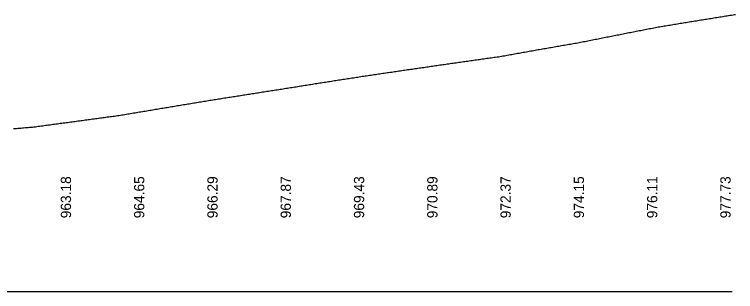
# Model space of a CAD drawing. Extents: x 1619269 to 1623088, y 1189107 to 1192385.
# Drawn here: x 1622586.5 to 1623078.6, y 1190356.6 to 1190545.7 of the extents above; entities that cross this region are included whole.
import ezdxf

# ---------------------------------------------------------------- set-up
doc = ezdxf.new("R2010")
doc.units = 0
for name, color, linetype in [('RD_DDB_Profile_EX', 7, 'Continuous'), ('RD_DDB_StripGrade', 7, 'Continuous'), ('RD_GPK_Profile_Cell', 7, 'Continuous')]:
    doc.layers.add(name, color=color, linetype=linetype)

msp = doc.modelspace()

# ---------------------------------------------------------------- linework, layer by layer
at = {"layer": 'RD_DDB_Profile_EX'}
for points in [[(1623024.84, 1190536.95), (1623025.84, 1190537.13), (1623026.84, 1190537.29), (1623027.84, 1190537.46), (1623028.84, 1190537.62), (1623029.84, 1190537.79), (1623030.84, 1190537.95), (1623031.84, 1190538.12), (1623032.84, 1190538.28), (1623033.84, 1190538.45), (1623034.84, 1190538.61), (1623035.84, 1190538.78), (1623036.84, 1190538.94), (1623037.84, 1190539.1), (1623038.84, 1190539.27), (1623039.84, 1190539.43), (1623040.84, 1190539.59), (1623041.84, 1190539.76), (1623042.84, 1190539.92), (1623043.84, 1190540.08), (1623044.84, 1190540.25), (1623045.84, 1190540.41), (1623046.84, 1190540.57), (1623047.84, 1190540.73), (1623048.84, 1190540.9), (1623049.84, 1190541.06), (1623050.84, 1190541.22), (1623051.84, 1190541.38), (1623052.84, 1190541.54), (1623053.84, 1190541.71), (1623054.84, 1190541.87), (1623055.84, 1190542.03), (1623056.84, 1190542.19), (1623057.84, 1190542.35), (1623058.84, 1190542.51), (1623059.84, 1190542.67), (1623060.84, 1190542.83), (1623061.84, 1190543), (1623062.84, 1190543.16), (1623063.84, 1190543.32), (1623064.84, 1190543.48), (1623065.84, 1190543.64), (1623066.84, 1190543.8), (1623067.84, 1190543.96), (1623068.84, 1190544.12), (1623069.84, 1190544.28), (1623070.84, 1190544.44), (1623071.84, 1190544.6), (1623072.84, 1190544.75), (1623073.84, 1190544.91), (1623074.84, 1190545.07), (1623075.84, 1190545.23), (1623076.84, 1190545.39), (1623077.84, 1190545.55), (1623078.57, 1190545.66)], [(1622924.84, 1190518.24), (1622925.84, 1190518.42), (1622926.84, 1190518.6), (1622927.84, 1190518.78), (1622928.84, 1190518.96), (1622929.84, 1190519.14), (1622930.84, 1190519.32), (1622931.84, 1190519.5), (1622932.84, 1190519.67), (1622933.84, 1190519.85), (1622934.84, 1190520.03), (1622935.84, 1190520.21), (1622936.84, 1190520.39), (1622937.84, 1190520.56), (1622938.84, 1190520.74), (1622939.84, 1190520.92), (1622940.84, 1190521.1), (1622941.84, 1190521.27), (1622942.84, 1190521.45), (1622943.84, 1190521.63), (1622944.84, 1190521.8), (1622945.84, 1190521.98), (1622946.84, 1190522.16), (1622947.84, 1190522.33), (1622948.84, 1190522.51), (1622949.84, 1190522.68), (1622950.84, 1190522.86), (1622951.84, 1190523.04), (1622952.84, 1190523.21), (1622953.84, 1190523.39), (1622954.84, 1190523.56), (1622955.84, 1190523.74), (1622956.84, 1190523.91), (1622957.84, 1190524.09), (1622958.84, 1190524.26), (1622959.84, 1190524.44), (1622960.84, 1190524.61), (1622961.84, 1190524.78), (1622962.84, 1190524.96), (1622963.84, 1190525.13), (1622964.84, 1190525.31), (1622965.84, 1190525.48), (1622966.84, 1190525.65), (1622967.84, 1190525.83), (1622968.84, 1190526), (1622969.84, 1190526.17), (1622970.84, 1190526.34), (1622971.84, 1190526.52), (1622972.84, 1190526.69), (1622973.84, 1190526.89), (1622974.84, 1190527.09), (1622975.84, 1190527.29), (1622976.84, 1190527.49), (1622977.84, 1190527.69), (1622978.84, 1190527.89), (1622979.84, 1190528.08), (1622980.84, 1190528.28), (1622981.84, 1190528.48), (1622982.84, 1190528.68), (1622983.84, 1190528.88), (1622984.84, 1190529.08), (1622985.84, 1190529.28), (1622986.84, 1190529.48), (1622987.84, 1190529.67), (1622988.84, 1190529.87), (1622989.84, 1190530.07), (1622990.84, 1190530.27), (1622991.84, 1190530.47), (1622992.84, 1190530.66), (1622993.84, 1190530.86), (1622994.84, 1190531.06), (1622995.84, 1190531.26), (1622996.84, 1190531.46), (1622997.84, 1190531.65), (1622998.84, 1190531.85), (1622999.84, 1190532.05), (1623000.84, 1190532.24), (1623001.84, 1190532.44), (1623002.84, 1190532.64), (1623003.84, 1190532.84), (1623004.84, 1190533.03), (1623005.84, 1190533.23), (1623006.84, 1190533.43), (1623007.84, 1190533.62), (1623008.84, 1190533.82), (1623009.84, 1190534.02), (1623010.84, 1190534.21), (1623011.84, 1190534.41), (1623012.84, 1190534.61), (1623013.84, 1190534.8), (1623014.84, 1190535), (1623015.84, 1190535.19), (1623016.84, 1190535.39), (1623017.84, 1190535.58), (1623018.84, 1190535.78), (1623019.84, 1190535.98), (1623020.84, 1190536.17), (1623021.84, 1190536.37), (1623022.84, 1190536.56), (1623023.84, 1190536.76), (1623024.84, 1190536.95)], [(1622824.84, 1190503.59), (1622825.84, 1190503.74), (1622826.84, 1190503.89), (1622827.84, 1190504.03), (1622828.84, 1190504.18), (1622829.84, 1190504.33), (1622830.84, 1190504.48), (1622831.84, 1190504.63), (1622832.84, 1190504.78), (1622833.84, 1190504.92), (1622834.84, 1190505.07), (1622835.84, 1190505.22), (1622836.84, 1190505.37), (1622837.84, 1190505.51), (1622838.84, 1190505.66), (1622839.84, 1190505.81), (1622840.84, 1190505.95), (1622841.84, 1190506.1), (1622842.84, 1190506.25), (1622843.84, 1190506.39), (1622844.84, 1190506.54), (1622845.84, 1190506.68), (1622846.84, 1190506.83), (1622847.84, 1190506.98), (1622848.84, 1190507.12), (1622849.84, 1190507.27), (1622850.84, 1190507.41), (1622851.84, 1190507.56), (1622852.84, 1190507.7), (1622853.84, 1190507.85), (1622854.84, 1190507.99), (1622855.84, 1190508.14), (1622856.84, 1190508.28), (1622857.84, 1190508.43), (1622858.84, 1190508.57), (1622859.84, 1190508.71), (1622860.84, 1190508.86), (1622861.84, 1190509), (1622862.84, 1190509.14), (1622863.84, 1190509.29), (1622864.84, 1190509.43), (1622865.84, 1190509.57), (1622866.84, 1190509.72), (1622867.84, 1190509.86), (1622868.84, 1190510.01), (1622869.84, 1190510.15), (1622870.84, 1190510.3), (1622871.84, 1190510.44), (1622872.84, 1190510.59), (1622873.84, 1190510.73), (1622874.84, 1190510.88), (1622875.84, 1190511.02), (1622876.84, 1190511.17), (1622877.84, 1190511.31), (1622878.84, 1190511.46), (1622879.84, 1190511.6), (1622880.84, 1190511.75), (1622881.84, 1190511.89), (1622882.84, 1190512.03), (1622883.84, 1190512.18), (1622884.84, 1190512.32), (1622885.84, 1190512.47), (1622886.84, 1190512.61), (1622887.84, 1190512.75), (1622888.84, 1190512.9), (1622889.84, 1190513.04), (1622890.84, 1190513.18), (1622891.84, 1190513.32), (1622892.84, 1190513.47), (1622893.84, 1190513.61), (1622894.84, 1190513.75), (1622895.84, 1190513.89), (1622896.84, 1190514.04), (1622897.84, 1190514.18), (1622898.84, 1190514.32), (1622899.84, 1190514.46), (1622900.84, 1190514.6), (1622901.84, 1190514.74), (1622902.84, 1190514.89), (1622903.84, 1190515.03), (1622904.84, 1190515.17), (1622905.84, 1190515.31), (1622906.84, 1190515.45), (1622907.84, 1190515.59), (1622908.84, 1190515.73), (1622909.84, 1190515.87), (1622910.84, 1190516.01), (1622911.84, 1190516.15), (1622912.84, 1190516.29), (1622913.84, 1190516.43), (1622914.84, 1190516.57), (1622915.84, 1190516.71), (1622916.84, 1190516.85), (1622917.84, 1190516.99), (1622918.84, 1190517.16), (1622919.84, 1190517.34), (1622920.84, 1190517.52), (1622921.84, 1190517.7), (1622922.84, 1190517.88), (1622923.84, 1190518.06), (1622924.84, 1190518.24)], [(1622724.84, 1190487.88), (1622725.84, 1190488.03), (1622726.84, 1190488.19), (1622727.84, 1190488.35), (1622728.84, 1190488.51), (1622729.84, 1190488.67), (1622730.84, 1190488.83), (1622731.84, 1190488.99), (1622732.84, 1190489.15), (1622733.84, 1190489.3), (1622734.84, 1190489.46), (1622735.84, 1190489.62), (1622736.84, 1190489.78), (1622737.84, 1190489.94), (1622738.84, 1190490.09), (1622739.84, 1190490.25), (1622740.84, 1190490.41), (1622741.84, 1190490.57), (1622742.84, 1190490.72), (1622743.84, 1190490.88), (1622744.84, 1190491.04), (1622745.84, 1190491.19), (1622746.84, 1190491.35), (1622747.84, 1190491.51), (1622748.84, 1190491.66), (1622749.84, 1190491.82), (1622750.84, 1190491.98), (1622751.84, 1190492.13), (1622752.84, 1190492.29), (1622753.84, 1190492.45), (1622754.84, 1190492.6), (1622755.84, 1190492.76), (1622756.84, 1190492.91), (1622757.84, 1190493.07), (1622758.84, 1190493.22), (1622759.84, 1190493.38), (1622760.84, 1190493.54), (1622761.84, 1190493.69), (1622762.84, 1190493.85), (1622763.84, 1190494), (1622764.84, 1190494.16), (1622765.84, 1190494.31), (1622766.84, 1190494.47), (1622767.84, 1190494.62), (1622768.84, 1190494.78), (1622769.84, 1190494.94), (1622770.84, 1190495.1), (1622771.84, 1190495.26), (1622772.84, 1190495.42), (1622773.84, 1190495.58), (1622774.84, 1190495.74), (1622775.84, 1190495.9), (1622776.84, 1190496.06), (1622777.84, 1190496.22), (1622778.84, 1190496.38), (1622779.84, 1190496.54), (1622780.84, 1190496.7), (1622781.84, 1190496.86), (1622782.84, 1190497.02), (1622783.84, 1190497.18), (1622784.84, 1190497.34), (1622785.84, 1190497.5), (1622786.84, 1190497.65), (1622787.84, 1190497.81), (1622788.84, 1190497.97), (1622789.84, 1190498.13), (1622790.84, 1190498.29), (1622791.84, 1190498.45), (1622792.84, 1190498.6), (1622793.84, 1190498.76), (1622794.84, 1190498.92), (1622795.84, 1190499.08), (1622796.84, 1190499.23), (1622797.84, 1190499.39), (1622798.84, 1190499.55), (1622799.84, 1190499.71), (1622800.84, 1190499.86), (1622801.84, 1190500.02), (1622802.84, 1190500.18), (1622803.84, 1190500.33), (1622804.84, 1190500.49), (1622805.84, 1190500.65), (1622806.84, 1190500.8), (1622807.84, 1190500.96), (1622808.84, 1190501.12), (1622809.84, 1190501.27), (1622810.84, 1190501.43), (1622811.84, 1190501.58), (1622812.84, 1190501.74), (1622813.84, 1190501.9), (1622814.84, 1190502.05), (1622815.84, 1190502.21), (1622816.84, 1190502.36), (1622817.84, 1190502.52), (1622818.84, 1190502.67), (1622819.84, 1190502.83), (1622820.84, 1190502.98), (1622821.84, 1190503.13), (1622822.84, 1190503.29), (1622823.84, 1190503.44), (1622824.84, 1190503.59)], [(1622624.84, 1190472.33), (1622625.84, 1190472.46), (1622626.84, 1190472.6), (1622627.84, 1190472.73), (1622628.84, 1190472.87), (1622629.84, 1190473), (1622630.84, 1190473.14), (1622631.84, 1190473.27), (1622632.84, 1190473.41), (1622633.84, 1190473.54), (1622634.84, 1190473.68), (1622635.84, 1190473.81), (1622636.84, 1190473.95), (1622637.84, 1190474.08), (1622638.84, 1190474.22), (1622639.84, 1190474.35), (1622640.84, 1190474.49), (1622641.84, 1190474.62), (1622642.84, 1190474.76), (1622643.84, 1190474.89), (1622644.84, 1190475.03), (1622645.84, 1190475.16), (1622646.84, 1190475.3), (1622647.84, 1190475.43), (1622648.84, 1190475.57), (1622649.84, 1190475.7), (1622650.84, 1190475.84), (1622651.84, 1190475.97), (1622652.84, 1190476.11), (1622653.84, 1190476.24), (1622654.84, 1190476.38), (1622655.84, 1190476.51), (1622656.84, 1190476.65), (1622657.84, 1190476.78), (1622658.84, 1190476.95), (1622659.84, 1190477.12), (1622660.84, 1190477.28), (1622661.84, 1190477.45), (1622662.84, 1190477.62), (1622663.84, 1190477.79), (1622664.84, 1190477.95), (1622665.84, 1190478.12), (1622666.84, 1190478.29), (1622667.84, 1190478.45), (1622668.84, 1190478.62), (1622669.84, 1190478.79), (1622670.84, 1190478.96), (1622671.84, 1190479.12), (1622672.84, 1190479.29), (1622673.84, 1190479.46), (1622674.84, 1190479.62), (1622675.84, 1190479.79), (1622676.84, 1190479.96), (1622677.84, 1190480.12), (1622678.84, 1190480.29), (1622679.84, 1190480.46), (1622680.84, 1190480.63), (1622681.84, 1190480.79), (1622682.84, 1190480.96), (1622683.84, 1190481.13), (1622684.84, 1190481.29), (1622685.84, 1190481.46), (1622686.84, 1190481.62), (1622687.84, 1190481.79), (1622688.84, 1190481.96), (1622689.84, 1190482.12), (1622690.84, 1190482.29), (1622691.84, 1190482.46), (1622692.84, 1190482.62), (1622693.84, 1190482.79), (1622694.84, 1190482.96), (1622695.84, 1190483.12), (1622696.84, 1190483.29), (1622697.84, 1190483.45), (1622698.84, 1190483.62), (1622699.84, 1190483.79), (1622700.84, 1190483.95), (1622701.84, 1190484.12), (1622702.84, 1190484.28), (1622703.84, 1190484.45), (1622704.84, 1190484.62), (1622705.84, 1190484.78), (1622706.84, 1190484.95), (1622707.84, 1190485.11), (1622708.84, 1190485.28), (1622709.84, 1190485.44), (1622710.84, 1190485.62), (1622711.84, 1190485.79), (1622712.84, 1190485.96), (1622713.84, 1190486.12), (1622714.84, 1190486.28), (1622715.84, 1190486.44), (1622716.84, 1190486.6), (1622717.84, 1190486.76), (1622718.84, 1190486.92), (1622719.84, 1190487.08), (1622720.84, 1190487.24), (1622721.84, 1190487.4), (1622722.84, 1190487.56), (1622723.84, 1190487.72), (1622724.84, 1190487.88)], [(1622585.84, 1190467.78), (1622586.84, 1190467.86), (1622587.84, 1190467.94), (1622588.84, 1190468.03), (1622589.84, 1190468.11), (1622590.84, 1190468.19), (1622591.84, 1190468.27), (1622592.84, 1190468.36), (1622593.84, 1190468.44), (1622594.84, 1190468.52), (1622595.84, 1190468.6), (1622596.84, 1190468.68), (1622597.84, 1190468.77), (1622598.84, 1190468.85), (1622599.84, 1190468.94), (1622600.84, 1190469.08), (1622601.84, 1190469.22), (1622602.84, 1190469.35), (1622603.84, 1190469.49), (1622604.84, 1190469.62), (1622605.84, 1190469.76), (1622606.84, 1190469.89), (1622607.84, 1190470.03), (1622608.84, 1190470.16), (1622609.84, 1190470.3), (1622610.84, 1190470.43), (1622611.84, 1190470.57), (1622612.84, 1190470.7), (1622613.84, 1190470.84), (1622614.84, 1190470.97), (1622615.84, 1190471.11), (1622616.84, 1190471.24), (1622617.84, 1190471.38), (1622618.84, 1190471.51), (1622619.84, 1190471.65), (1622620.84, 1190471.78), (1622621.84, 1190471.92), (1622622.84, 1190472.05), (1622623.84, 1190472.19), (1622624.84, 1190472.33)]]:
    msp.add_lwpolyline(points, dxfattribs=at)
at = {"layer": 'RD_GPK_Profile_Cell'}
msp.add_line((1621576.17, 1190356.62), (1623076.17, 1190356.62), dxfattribs=at)

# ---------------------------------------------------------------- texts
at = {"layer": 'RD_DDB_StripGrade'}
for s, p in [('963.18', (1622625.17, 1190406.62)), ('964.65', (1622675.17, 1190406.62)), ('966.29', (1622725.17, 1190406.62)), ('967.87', (1622775.17, 1190406.62)), ('969.43', (1622825.17, 1190406.62)), ('970.89', (1622875.17, 1190406.62)), ('972.37', (1622925.17, 1190406.62)), ('974.15', (1622975.17, 1190406.62)), ('976.11', (1623025.17, 1190406.62)), ('977.73', (1623075.17, 1190406.62))]:
    msp.add_text(s, height=7, rotation=90, dxfattribs=at).set_placement(p)

doc.saveas('drawing.dxf')
